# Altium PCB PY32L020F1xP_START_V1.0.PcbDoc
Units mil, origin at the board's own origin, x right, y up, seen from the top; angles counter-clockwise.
Board outline 2125 x 1150 mil, 2 copper layers (Top Layer, Bottom Layer); 27 components, 27 nets, 122 pads, 82 vias.
Unrouted connection lines stored in the file: 3.
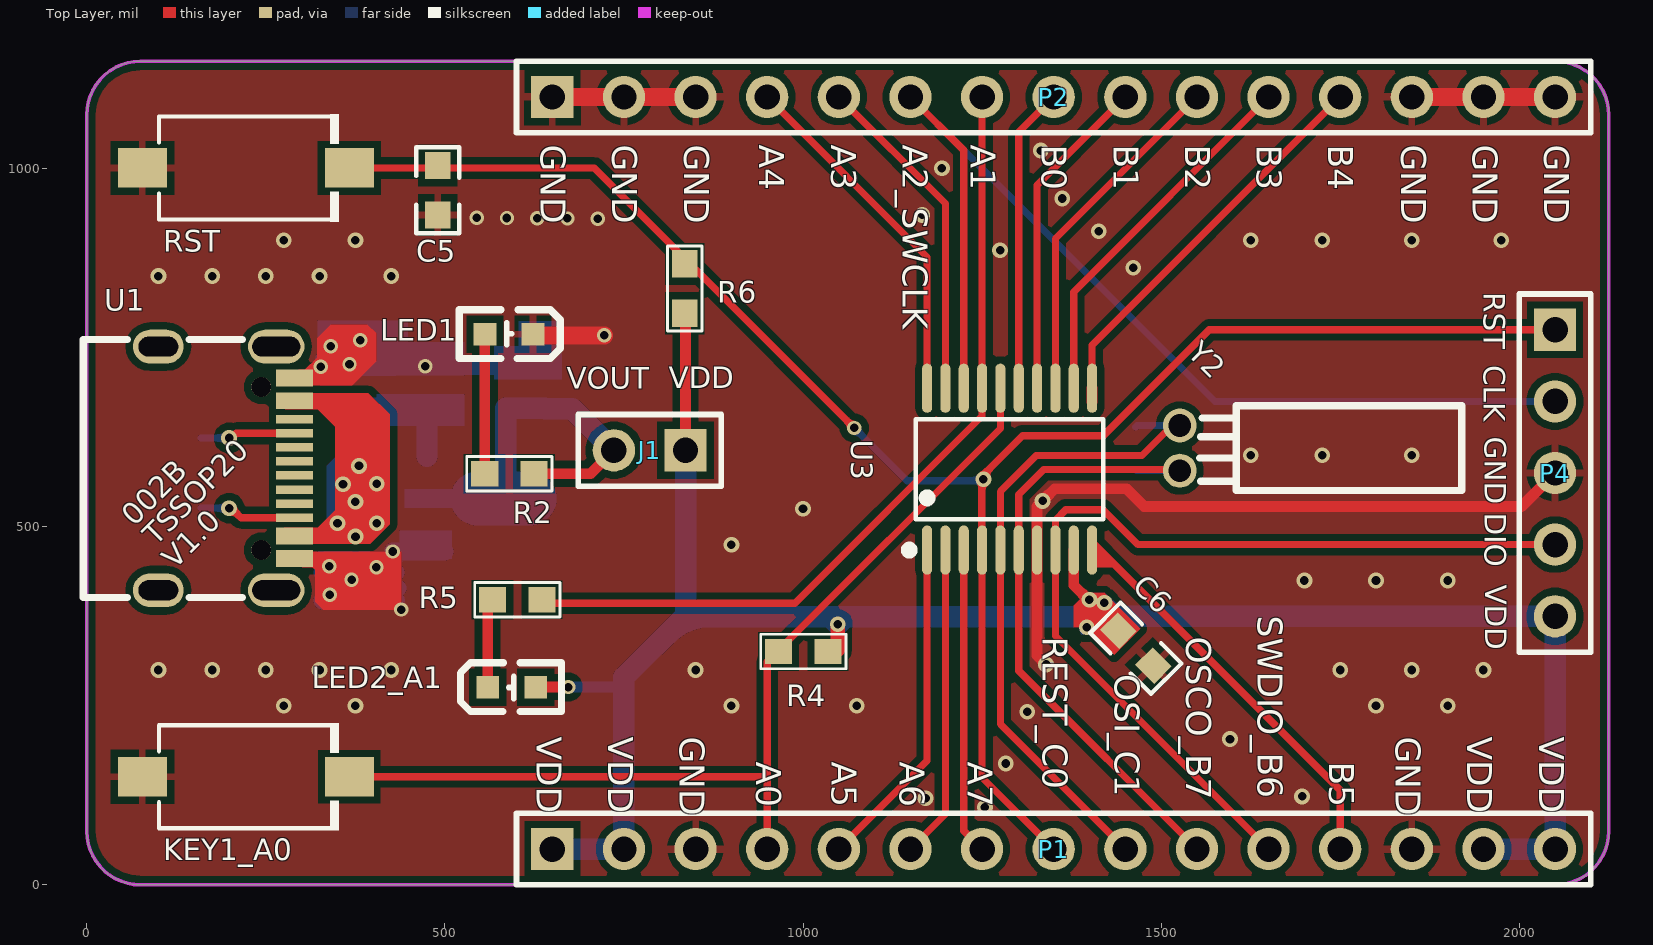
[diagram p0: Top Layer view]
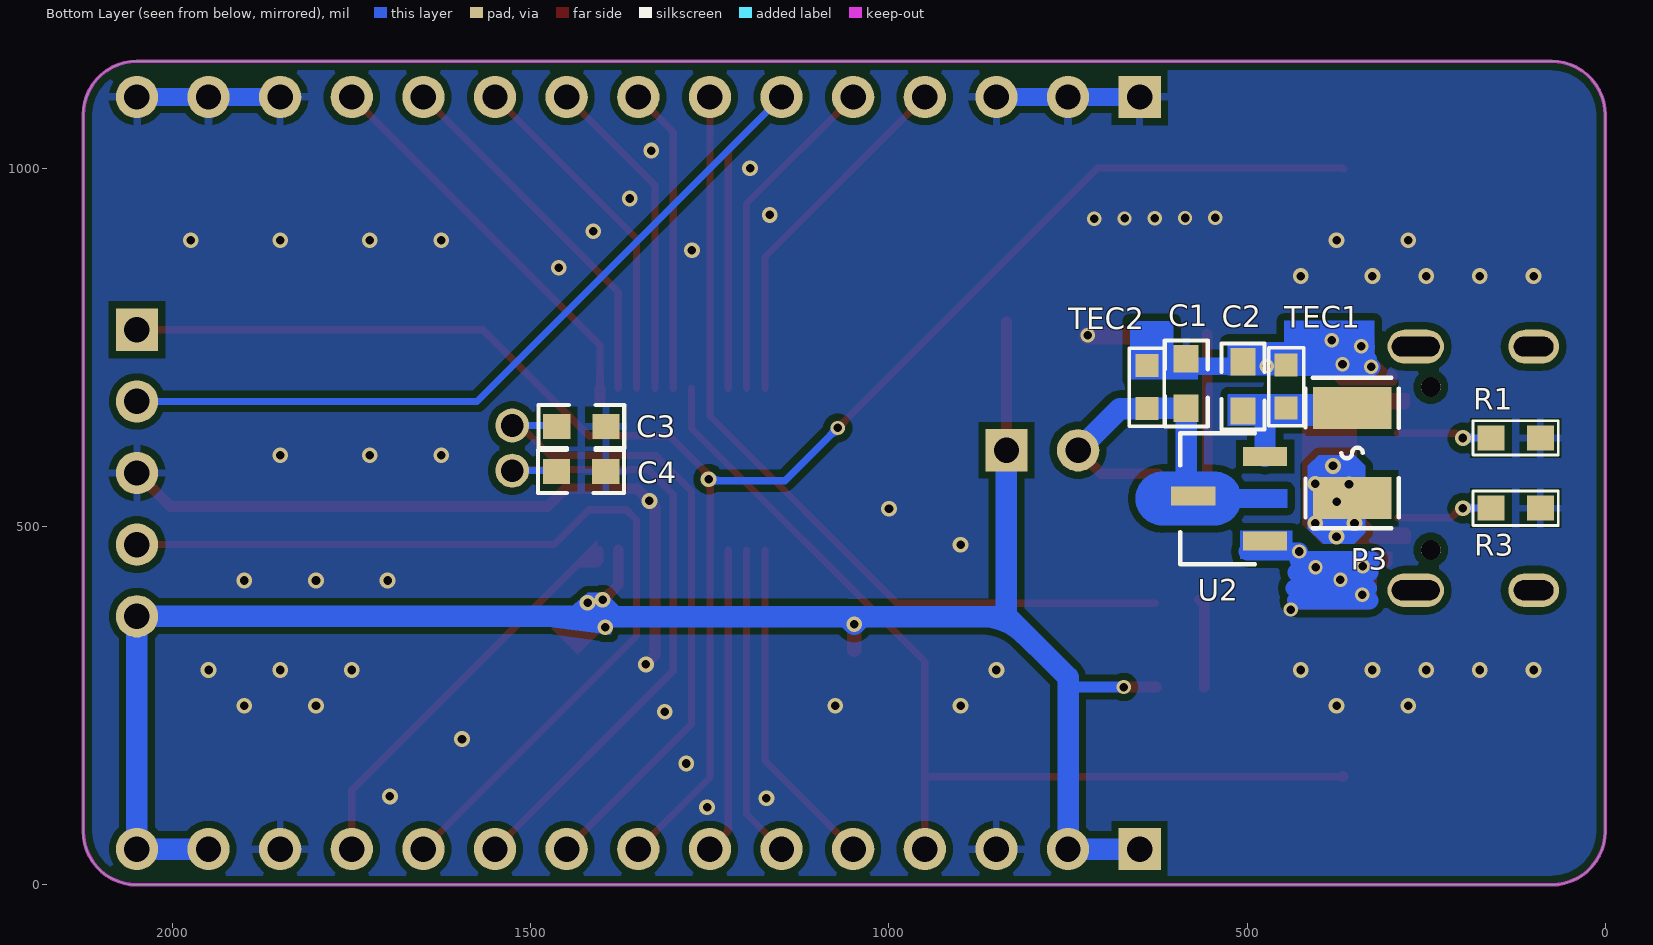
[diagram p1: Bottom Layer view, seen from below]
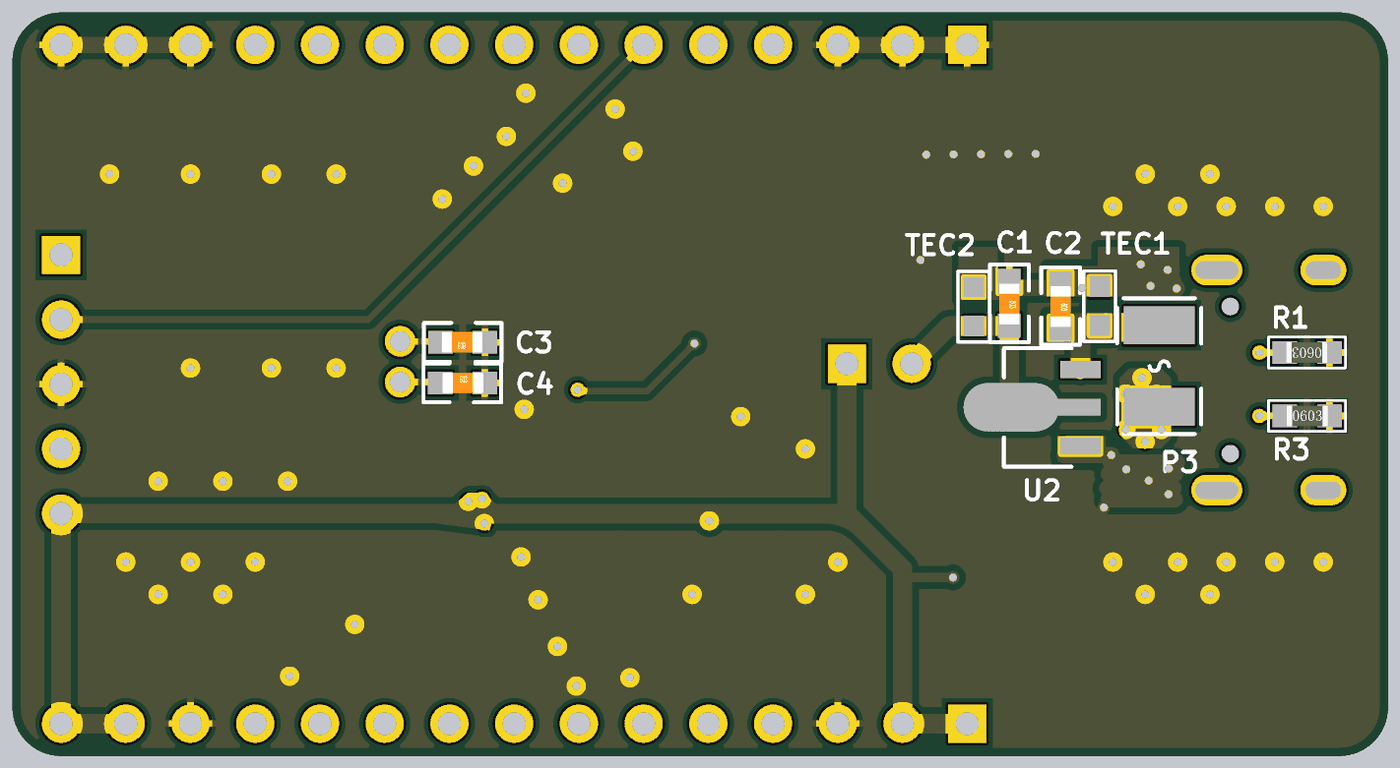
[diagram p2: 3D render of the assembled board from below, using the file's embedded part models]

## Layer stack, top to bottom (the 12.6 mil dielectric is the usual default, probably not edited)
Top Solder: solder mask 0.4, Solder Resist, Dk 3.5
Top Layer: signal copper 1.4
Dielectric1: dielectric 12.6, FR-4, Dk 4.8
Bottom Layer: signal copper 1.4
Bottom Solder: solder mask 0.4, Solder Resist, Dk 3.5

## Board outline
0,75 0,1075 cw(c75,1075) 75,1150 2050,1150 cw(c2050,1075) 2125,1075 2125,75 cw(c2050,75) 2050,0 75,0 cw(c75,75)

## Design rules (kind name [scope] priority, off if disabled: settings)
Clearance [All] p1: gap=10 ignorepadtopadclearanceinfootprint=FALSE
ComponentClearance [All] p1: gap=0 collisioncheckmode=3 verticalgap=0 showdistances=FALSE
HoleToHoleClearance [All] p1: gap=3 allowstackedmicrovias=TRUE
MinimumSolderMaskSliver [All] p1: minsoldermaskwidth=0
NetAntennae [All] p1: netantennaetolerance=6
PlaneConnect PlaneConnect_1 [IsVia] p1: planeconnectstyle=Direct reliefexpansion=20 reliefentries=4 reliefconductorwidth=10 reliefairgap=10
PlaneConnect [All] p2: planeconnectstyle=Relief reliefexpansion=20 reliefentries=4 reliefconductorwidth=10 reliefairgap=10
PolygonConnect PolygonConnect_1 [IsVia] p1: connectstyle=Direct reliefconductorwidth=10 reliefentries=4 polygonreliefangle="90 Angle" airgapwidth=10
PolygonConnect [All] p2: connectstyle=Relief reliefconductorwidth=10 reliefentries=4 polygonreliefangle="90 Angle" airgapwidth=10
RoutingCorners [All] p1: cornerstyle=45-Degree minsetback=10 maxsetback=100
RoutingVias [All] p1: holewidth=28 width=50 viastyle="Through Hole" minholewidth=10 minwidth=50 maxholewidth=28 maxwidth=50
SilkToSilkClearance [All] p1: silktosilkclearance=0
SilkToSolderMaskClearance [IsPad] p1: minsilkscreentomaskgap=0 clearancetoexposedcopper=TRUE
SolderMaskExpansion [All] p1: expansion=4 istentingtop=FALSE
UnRoutedNet [All] p1: checkbadconnections=TRUE
Width [All] p1: maxlimit=30 minlimit=2 preferedwidth=8
21 further rules are at their usual default settings.

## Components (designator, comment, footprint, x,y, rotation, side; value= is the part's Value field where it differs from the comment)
C1 "0.1uF/50V" 0603C 585,700 r270 bottom
C2 "0.1uF/50V" 0603C 505.73,695.96 r270 bottom value=2.2uF
C3 "22pF" 0603C 1429.5,639.95 r0 bottom
C4 "22pF" 0603C 1429.89,577.02 r180 bottom
C5 "0.1uF/50V" 0603C 490.02,969.74 r90 top value=2.2uF
C6 "0.1uF/50V" 0603C 1464.62,330.43 r135 top value=2.2uF
J1 "JUMP" HDR1X2 835.93,606.76 r180 top
KEY1_A0 "1TS002B-2600-5001" SW 175,150 r0 top (schematic designator KEY1)
LED1 "RED" 0603_LED 575,770 r180 top
LED2_A1 "GREEN" 0603_LED 607.65,275.04 r0 top (schematic designator LED2)
P1 "Header 15" HDR1X15 650,50 r0 top
P2 "Header 15" HDR1X15 650,1100 r0 top
P3 "SMD1210P005TF" SDM1210P005TF 375,600 r90 bottom
P4 "Debug" HDR1X5 2050,775 r270 top
R1 "5.1k" 0603R 125,625 r0 bottom value=10K
R2 "470Ω" 0603R 590,575 r180 top value=10K
R3 "5.1K" 0603R 125,525 r180 bottom value=10K
R4 "1.5K" 0603R 1000.44,326.82 r180 top value=10K
R5 "680Ω" 0603R 601.06,397.12 r0 top value=10K
R6 "10K" 0603R 833.85,832.57 r270 top
RST "1TS002B-2600-5001" SW 175,1000 r0 top (schematic designator RST1)
TEC1 "10uF" 0603 445.51,695.66 r270 bottom value=10uF/16V
TEC2 "10uF" 0603 640,695 r270 bottom value=10uF/16V
U1 "KH-TYPE-C-16P" USB-C-SMD_KH-TYPE-C-16P 150,575 r270 top locked
U2 "LM1117-3.3" LM1117-3.3 475,480 r180 bottom
U3 "PY32F002B_F1" TSSOP20 1173.23,467.39 r0 top locked
Y2 "32.768KHz" 32768KHZ_2 1649.77,605.82 r180 top value=X503225MSB2GI

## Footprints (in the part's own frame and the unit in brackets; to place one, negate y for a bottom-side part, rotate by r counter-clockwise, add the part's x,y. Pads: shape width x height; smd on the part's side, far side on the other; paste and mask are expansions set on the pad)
0603 [mil]
  rect 32x32 smd: 1(30,0) 2(-30,0)
  silkscreen extent -54,-25 55,25
0603_LED [mil]
  rect 31.5x31.5 smd: 1(19,1) 2(-48,1)
  silkscreen extent -86,-33 55,35
0603C [mil]
  rect 38x35 smd: 1(-34.5,0) 2(34.5,0)
  silkscreen extent -60,-30 60,30, body extent -31,-16 32,16, height 12
0603R [mil]
  rect 38x35 smd: 1(-34.5,1) 2(34.5,1)
  silkscreen extent -59,-23 59,25, body extent -31,-15 32,17, height 18
32768KHZ_2 [mm]
  round 1.2 hole 0.8: 1(3.142,-0.903) 2(3.142,0.697)
  silkscreen extent -6.86,-1.6 2.44,1.4
HDR1X2 [mm] "Connector; Header; 2 Position"
  rect 1.5x1.5 hole 0.9: 1(0,0)
  round 1.5 hole 0.9: 2(2.54,0)
  silkscreen extent -1.27,-1.27 3.81,1.27
HDR1X5 [mm] "Connector; Header; 5 Position"
  rect 1.5x1.5 hole 0.9: 1(0,0)
  round 1.5 hole 0.9: 2(2.54,0) 3(5.08,0) 4(7.62,0) 5(10.16,0)
  silkscreen extent -1.27,-1.27 11.43,1.27
HDR1X15 [mm]
  rect 1.5x1.5 hole 0.9: 1(0,0)
  round 1.5 hole 0.9: 2(2.54,0) 3(5.08,0) 4(7.62,0) 5(10.16,0) 6(12.7,0) 7(15.24,0) 8(17.78,0) 9(20.32,0) 10(22.86,0) 11(25.4,0) 12(27.94,0) 13(30.48,0) 14(33.02,0) 15(35.56,0)
  silkscreen extent -1.27,-1.27 36.83,1.27
LM1117-3.3 [mm]
  rect 1.575x0.672 smd: 1(0,0) 2(-2.55,1.598) 3(0,3)
  Top Layer region: -3.64,2.459 -1.785,2.459 -1.741,2.458 -1.696,2.455 -1.652,2.449 -1.608,2.442 -1.565,2.433 -1.522,2.421 -1.479,2.408 -1.437,2.393 -1.396,2.375 -1.356,2.356 -1.317,2.335 -1.279,2.312 -1.241,2.288 -1.206,2.261 -1.171,2.233 -1.138,2.204 -1.106,2.173 -1.075,2.14 -1.047,2.106 -1.019,2.071 -0.994,2.034 -0.97,1.996 -0.948,1.958 -0.928,1.918 -0.91,1.839 0.788,1.839 0.788,1.179 -0.91,1.179 -0.928,1.099 -0.948,1.06 -0.97,1.021 -0.994,0.983 -1.019,0.947 -1.047,0.911 -1.075,0.877 -1.106,0.845 -1.138,0.814 -1.171,0.784 -1.206,0.756 -1.241,0.73 -1.279,0.705 -1.317,0.682 -1.356,0.661 -1.396,0.642 -1.437,0.625 -1.479,0.609 -1.522,0.596 -1.565,0.585 -1.608,0.575 -1.652,0.568 -1.696,0.563 -1.741,0.56 -1.785,0.559 -3.64,0.559 -3.684,0.56 -3.728,0.563 -3.773,0.568 -3.817,0.575 -3.86,0.585 -3.903,0.596 -3.946,0.609 -3.988,0.625 -4.029,0.642 -4.069,0.661 -4.108,0.682 -4.146,0.705 -4.183,0.73 -4.219,0.756 -4.254,0.784 -4.287,0.814 -4.319,0.845 -4.349,0.877 -4.378,0.911 -4.405,0.947 -4.431,0.983 -4.455,1.021 -4.477,1.06 -4.497,1.099 -4.515,1.14 -4.531,1.181 -4.546,1.224 -4.558,1.266 -4.568,1.31 -4.577,1.353 -4.583,1.398 -4.587,1.442 -4.589,1.486 -4.589,1.531 -4.587,1.575 -4.583,1.62 -4.577,1.664 -4.568,1.708 -4.558,1.751 -4.546,1.794 -4.531,1.836 -4.515,1.877 -4.497,1.918 -4.477,1.958 -4.455,1.996 -4.431,2.034 -4.405,2.071 -4.378,2.106 -4.349,2.14 -4.319,2.173 -4.287,2.204 -4.254,2.233 -4.219,2.261 -4.183,2.288 -4.146,2.312 -4.108,2.335 -4.069,2.356 -4.029,2.375 -3.988,2.393 -3.946,2.408 -3.903,2.421 -3.86,2.433 -3.817,2.442 -3.773,2.449 -3.728,2.455 -3.684,2.458
  silkscreen extent -3.01,-0.83 -0.35,3.83
SDM1210P005TF [mm]
  rect 1.485x2.781 smd: 1(-1.524,-0.549) 2(1.676,-0.549)
  silkscreen extent -2.59,-2.2 2.74,1.1
SW [mm]
  rect 1.74x1.4 smd: 1(-2.476,0.024) 2(4.864,0.024)
  silkscreen extent -1.88,-1.88 4.5,1.93
TSSOP20 [mm]
  oval 0.364x1.742 smd: 1(0,0) 2(0.65,0) 3(1.3,0) 4(1.95,0) 5(2.6,0) 6(3.25,0) 7(3.9,0) 8(4.55,0) 9(5.2,0) 10(5.85,0) 11(5.85,5.742) 12(5.2,5.742) 13(4.55,5.742) 14(3.9,5.742) 15(3.25,5.742) 16(2.6,5.742) 17(1.95,5.742) 18(1.3,5.742) 19(0.65,5.742) 20(0,5.742)
  silkscreen extent -0.78,-0.15 6.25,4.64
USB-C-SMD_KH-TYPE-C-16P [mm] "https://item.szlcsc.com/747093.html"
  oval 1.2x2 hole 0.7 slot 1.7 at 90 deg: 1(-4.484,2.908) 2(4.156,2.908)
  oval 1.2x1.8 hole 0.7 slot 1.4 at 90 deg: 3(-4.484,-1.272) 4(4.156,-1.272)
  rect 0.3x1.3 smd: A1(-3.514,3.558) A4(-2.714,3.558) A5(-1.414,3.558) A6(-0.414,3.558) A7(0.086,3.558) A8(1.086,3.558) A9(2.386,3.558) A12(3.186,3.558) B1(2.886,3.558) B4(2.086,3.558) B5(1.586,3.558) B6(0.586,3.558) B7(-0.914,3.558) B8(-1.914,3.558) B9(-2.414,3.558) B12(-3.214,3.558)
  round 0.7 hole 0.7 unplated: ""(-3.054,2.378) ""(2.726,2.378)
  silkscreen extent -4.74,-3.94 4.41,1.72

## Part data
C1 C3 C4: library part Cap, "Capacitor"
C2 C5 C6: library part CAP, "Capacitor"
KEY1_A0 RST: BOM_JLCPCB Part Class="Extended Part", BOM_Manufacturer=HYP
LED1 LED2_A1: library part PDI-E803_Dup1
P1 P2: "Header, 15-Pin"
P4: library part CON5
R1 R3: library part Res_1, "Resistor"
R2 R4 R5 R6: library part Res, "Resistor"
TEC1 TEC2: library part 贴片钽电容
U1: BOM_JLCPCB Part Class="Extended Part", BOM_Manufacturer="Shenzhen Kinghelm Elec"
Y2: library part CRYSTAL_1, "Crystal"

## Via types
v1: diameter 22, hole 12, Top Layer to Bottom Layer, 63 vias
v2: diameter 20, hole 12, Top Layer to Bottom Layer, tented both sides, 19 vias

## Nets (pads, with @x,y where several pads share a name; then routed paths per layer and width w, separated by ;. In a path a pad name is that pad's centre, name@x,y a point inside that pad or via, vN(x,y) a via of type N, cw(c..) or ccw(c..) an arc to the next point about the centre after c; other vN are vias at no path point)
GND: C1.1 C2.1 C3.1 C4.2 C5.1 C6.1 KEY1_A0.1 LED1.2 P1.3 P1.13 P2.1 P2.2 P2.3 P2.13 P2.14 P2.15 P4.3 R1.1 R3.2 RST.1 TEC1.2 TEC2.2 U1.A1 U1.A12 U1.B1 U1.B12 U2.1 U3.7 | length 2885.1
  Top Layer w15: v1(1339.37,307.86) 1326.77,320.46 U3.7 1326.77,528.4 v1(1334.48,536.1) 1351.4,553.03 1451.6,553.03 1476.51,528.12 2003.12,528.12 P4.3
  Top Layer w25: 640.27,767.19 v2(722.45,767.19) ; P2.1 P2.2 ; P2.2@750.43,1100.43 P2.2 ; P2.3 P2.2 ; P2.13 P2.14 ; P2.14@1950.71,1100.71 P2.14 ; P2.15 P2.14
  Bottom Layer w25: 326,453.82 428.42,453.82 ; v2@326.09,723.23 428.51,723.23 ; 328.92,436.36 431.34,436.36 ; 329.32,396.82 431.74,396.82 ; 330.94,733.32 TEC1.2@433.36,733.32 ; 331.34,414.17 433.76,414.17 ; v2@334.16,750.67 436.58,750.67 ; 426.15,740.18 472.64,740.18 ; v2(427.37,465.41) 499.29,465.41 ; v2(472.64,724.05) 574.55,724.05 578.5,728 580,728 585,733 C1.1@585,733.5 ; C1.1 C1.1@585,733.5 ; TEC2.2 636.5,728.5 590,728.5 C1.1@585,733.5 ; P2.1 P2.2 ; P2.2@750.06,1100.05 P2.2 ; P2.3 P2.2 ; P2.13 P2.14 ; P2.14@1950.64,1100.63 P2.14 ; P2.15 P2.14
  other v1: 1253.97,108.24 1171.13,120.96 1696.82,123.47 1283.11,169.44 1596.18,203.53 1313.03,241.63 275,250 375,250 900,250 1075,250 1800,250 1900,250 100,300 175,300 250,300 325,300 425,300 850,300 1750,300 1850,300 1950,300 1700,425 1800,425 1900,425 900,475 1000,525 1625,600 1725,600 1850,600 100,850 175,850 250,850 325,850 425,850 1461.07,861.47 1275.14,886.08 275,900 375,900 1625,900 1725,900 1850,900 1975,900 1412.75,912.55 1166.48,935.39 1362.06,958.38 1193.95,1000.68 1331.9,1025.21
  other v2: 439.02,384.37 339.07,404.87 369.67,425.96 404.39,443.45 338.55,444.72 326.47,723.2 366.83,727.05 340.51,751.8 381.8,760.41 628.82,930.77 671.05,930.48 713.28,930.18 544.36,931.36 586.59,931.07
MCU_RST: C5.2 P1.8 P4.1 R6.1 RST.2 U3.4 | length 2516.2
  Top Layer w10: RST.2@365.03,999.5 RST.2 708.48,1000.96 v2(1071.47,637.98) ; P1.8 1250,150 U3.4 1249.64,467.75 1249.64,564.24 v1(1251.86,566.47) 1251.86,572.58 1306.38,627.1 1419.26,627.1 1567.17,775 P4.1
  Bottom Layer w10: v2(1071.47,637.98) 1145.13,564.32 1249.71,564.32 v1(1251.86,566.47)
MCU_VDD: C6.2 J1.1 LED2_A1.1 P1.1 P1.2 P1.14 P1.15 P4.5 R4.1 R6.2 U3.9 | length 2816.4
  Top Layer w15: LED2_A1.1 626.72,276.11 672,276.11 v2(672.07,276.18) ; J1.1 R6.2@835.93,786.33 ; U3.9 1377.95,418.34 C6.2@1437.5,358.8
  Top Layer w20: R4.1@1048.53,328.05 v1(1048.53,363.77)
  Bottom Layer w15: v2(672.07,276.18) 742.2,276.18 750,268.38
  Bottom Layer w30: P1.1 P1.2 750,268.38 750,289.68 834.91,374.59 ; J1.1 835.93,375.61 834.91,374.59 ; P1.14 P1.15 P4.5@2050,374.59 ; P4.5@2050,375.11 1397.35,375.11 1396.83,374.59 1059.34,374.59 v1(1048.53,363.77) 1037.71,374.59 834.91,374.59
  other v1: 1396.01,359.54 1420.81,393.92 1399.85,397.95
NetC1_2: C1.2 J1.2 R2.1 TEC2.1 U2.2 | length 431.4
  Top Layer w15: R2.1 703.17,574 J1.2
  Bottom Layer w30: U2.2 583.23,542.9 585,544.67 C1.2 585.25,665.25 639.75,665.25 TEC2.1 677.68,665 J1.2
NetC2_2: C2.2 P3.2 TEC1.1 U2.3 | length 193.8
  Bottom Layer w30: P3.2 353.89,665.49 478.24,665.49 475,662.25 U2.3
NetLED1_1: LED1.1 R2.2 | length 195.2
  Top Layer w15: R2.2 555.75,574.25 555.75,768.75 LED1.1
NetLED2_2: LED2_A1.2 R5.1 | length 124.9
  Top Layer w15: LED2_A1.2 559.65,391.22 R5.1
NetR1_2: R1.2 U1.A5 | length 133.4
  Top Layer w10: v1(198.63,623.94) 201.88,623.94 208.61,630.67 U1.A5
  Bottom Layer w10: R1.2 159.56,623.94 v1(198.63,623.94)
NetR3_1: R3.1 U1.B5 | length 142.6
  Top Layer w10: v1(198.63,526) 201.88,526 215.32,512.56 U1.B5
  Bottom Layer w10: R3.1 R3.1 204.97,526.04 v1@205,526
OSCIN: C3.2 P1.9 U3.5 Y2.1 | length 922.7
  Top Layer w10: P1.9 1275.59,224.41 U3.5 1275.59,549.45 1325.51,599.37 1473.24,599.37 1515.24,641.37 Y2.1
  Bottom Layer w10: C3.2@1464.47,639.43 1466.4,641.37 Y2.1
OSCOUT: C4.1 P1.10 U3.6 Y2.2 | length 900.4
  Top Layer w10: Y2.2@1526.59,579.83 1336.09,579.83 1301.18,544.92 U3.6 1301.18,298.82 P1.10
  Bottom Layer w10: C4.1@1464.19,580.06 1465.88,578.37 Y2.2
PA0: KEY1_A0.2 P1.4 R4.2 U3.16 | length 1363
  Top Layer w10: KEY1_A0.2 948.16,150.96 950,152.8 ; P1.4 950,152.8 ; U3.16 1275.59,637.36 966.81,328.58 950,311.77 950,291.8 950,152.8
  Top Layer w15: KEY1_A0.2@366.22,151.24 KEY1_A0.2
PA1: P2.7 R5.2 U3.17 | length 1175.6
  Top Layer w10: R5.2@628.15,393.14 988.65,393.14 1250,654.49 U3.17 P2.7
PA3: P2.5 U3.19 | length 468.2
  Top Layer w10: P2.5 1198.82,951.18 U3.19
PA4: P2.4 U3.20 | length 499
  Top Layer w10: P2.4 1173.23,876.77 U3.20
PA5: P1.5 U3.1 | length 468.4
  Top Layer w10: P1.5 1173.23,173.23 U3.1
PA6: P1.6 U3.2 | length 437.6
  Top Layer w10: P1.6 1198.82,98.82 U3.2
PA7: P1.7 U3.3 | length 428
  Top Layer w10: U3.3 1224.41,75.59 P1.7
PB0: P2.8 U3.15 | length 426.8
  Top Layer w10: U3.15 1301.18,1051.18 P2.8
PB1: P2.9 U3.14 | length 457.6
  Top Layer w10: U3.14 1326.77,976.77 P2.9
PB2: P2.10 U3.13 | length 488.4
  Top Layer w10: U3.13 1352.36,902.36 P2.10
PB3: P2.11 U3.12 | length 519.2
  Top Layer w10: U3.12 1377.95,827.95 P2.11
PB4: P2.12 U3.11 | length 569.2
  Top Layer w10: U3.11 1403.54,753.54 P2.12
  Top Layer w15: U3.11@1403.54,674.35 U3.11
PB5: P1.12 U3.10 | length 576.3
  Top Layer w10: U3.10 1403.54,452.21 1407.42,448.34 1433.7,448.34 1750,132.03 P1.12
SWCLK: P2.6 P4.2 U3.18 | length 1513.4
  Top Layer w10: P2.6 1224.41,1025.59 U3.18
  Bottom Layer w10: P2.6 1575,675 P4.2
SWDIO: P1.11 P4.4 U3.8 | length 1306.4
  Top Layer w10: P1.11 1352.36,347.64 U3.8 1352.36,509.33 1366.73,523.7 1418.79,523.7 1467.49,475 P4.4
Type_C: P3.1 U1.A4 U1.A9 U1.B4 U1.B9
  other v1: 375.16,486.24 350,505 405,505 375,535 357.76,559.32 405,560 380,585
pads on no net: U1. U1.1 U1.2 U1.3 U1.4 U1.A6 U1.A7 U1.A8 U1.B6 U1.B7 U1.B8

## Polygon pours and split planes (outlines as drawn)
GND on Top Layer "GND_L01_P001" (solid, remove dead copper, pour order 1): 0,1150 2125,1150 2125,0 0,0
GND on Bottom Layer "GND_L02_P002" (solid, pour order 2): 0,1150 2125,1150 2125,0 0,0

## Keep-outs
Keep-Out Layer:
  the board outline again, w5

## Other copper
Top Layer:
  region net PB5: 1407.42,481.61 1407.42,448.34 1440.7,448.34
  region net MCU_VDD: 1395.97,407.65 1377.78,389.47 1377.78,359.54 1396.01,359.54 1434.34,321.21 1470.74,357.62 1420.71,407.65
  region net GND: 300.52,443.72 315.07,443.72 318.97,439.82 318.97,395.54 330.15,384.37 439.02,384.37 439.02,465.34 298.86,465.34 297.6,464.09 297.6,446.64
  region net Type_C: 395.95,475.95 423.21,503.21 423.21,656.79 393.28,686.72 275.39,686.73 272.73,684.06 272.73,668.38 276.99,664.12 322.24,664.12 346.78,639.59 346.78,523.3 322.2,498.72 275.77,498.72 271.26,494.22 271.26,478.1 273.41,475.95
  region net GND: 304.63,719.24 321.57,736.17 321.57,763.14 340.71,782.29 391.89,782.29 403.8,770.37 403.8,731.17 370.53,697.9 293.72,697.9 290.09,701.54 290.09,713.35 295.97,719.24
Bottom Layer:
  rectangle net MCU_VDD: 1037.71,359.93 1065.51,389.57
  rectangle net NetC2_2: 426.15,640.68 527.23,684.91
  rectangle net GND: 436.54,455.06 510.09,494.83
  rectangle net GND: 568.19,705.42 663.56,752.27
  rectangle net GND: 426.15,710.95 527.23,758.27
  rectangle net GND: 322.13,716.28 448.42,787.73
  rectangle net NetC2_2: 404.82,641 526.62,685.05
  rectangle net GND: 602.93,705.42 663.56,787.41
  region net MCU_VDD: 1395.97,407.65 1377.05,388.73 1388.16,348.92 1476.61,360.55 1420.71,407.65
  region net Type_C: 350,600 335,585 335,491.64 350.71,475.93 393.56,475.93 415,497.38 415,585 400,600

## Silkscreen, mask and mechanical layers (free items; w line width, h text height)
Top Overlay:
  text "GND" at 633.9,1033.19 h35 r270
  text "GND" at 733.99,1033.19 h35 r270
  text "GND" at 834.08,1033.19 h35 r270
  text "A4" at 939.18,1033.19 h35 r270
  text "A3" at 1039.27,1033.19 h35 r270
  text "A2_SWCLK" at 1139.36,1033.19 h35 r270
  text "A1" at 1234.46,1033.19 h35 r270
  text "B0" at 1333.51,1033.19 h35 r270
  text "B1" at 1433.51,1033.19 h35 r270
  text "B2" at 1533.51,1033.19 h35 r270
  text "B3" at 1633.51,1033.19 h35 r270
  text "B4" at 1733.51,1033.19 h35 r270
  text "GND" at 1835.02,1033.19 h35 r270
  text "GND" at 1935.11,1033.19 h35 r270
  text "GND" at 2035.21,1033.19 h35 r270
  text "RST" at 1950.52,827.36 h30 r270
  text "CLK" at 1950.52,725.36 h30 r270
  text "VDD" at 812.47,693.15 h30
  text "VOUT" at 669.96,692.48 h30
  text "GND" at 1951.52,625.36 h30 r270
  text "DIO" at 1951.52,519.36 h30 r270
  text "002B" at 66.57,499.12 h30 r45
  text "TSSOP20" at 96.57,471.78 h30 r45
  text "V1.0" at 123.04,439.14 h30 r45
  text "VDD" at 1952.52,419.36 h30 r270
  text "SWDIO_B6" at 1635,375.78 h35 r270
  text "REST_C0" at 1335,346.62 h35 r270
  text "OSCO_B7" at 1535,346.62 h35 r270
  text "OSI_C1" at 1435,294.14 h35 r270
  text "VDD" at 628.28,206.67 h35 r270
  text "VDD" at 728.24,206.67 h35 r270
  text "GND" at 828.19,206.67 h35 r270
  text "GND" at 1827.75,206.67 h35 r270
  text "VDD" at 1927.71,206.67 h35 r270
  text "VDD" at 2027.67,206.67 h35 r270
  text "A0" at 935,171.68 h35 r270
  text "A5" at 1040,171.68 h35 r270
  text "A6" at 1135,171.68 h35 r270
  text "A7" at 1230,171.68 h35 r270
  text "B5" at 1735,171.68 h35 r270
